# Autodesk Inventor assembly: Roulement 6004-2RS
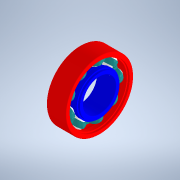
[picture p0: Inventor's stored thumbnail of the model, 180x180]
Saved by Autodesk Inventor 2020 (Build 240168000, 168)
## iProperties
Created: 2003-06
Part Number: Roulement 6004-2RS
Document SubType Name: Assembly
Designer: Bruno
Author: Bruno
Sending System: SolidWorks 2011
Last Author: Professeur
Last Saved: 2014-11-10
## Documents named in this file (5)
- D:\Téléchargements-2016-17\scoot_elec\pièces à assembler\ROULEMENT 6004-2RS\Roulement 6004-2RS.iam
- D:\Téléchargements-2016-17\scoot_elec\pièces à assembler\ROULEMENT 6004-2RS\Bague intérieure 6004-2RS.ipt
- D:\Téléchargements-2016-17\scoot_elec\pièces à assembler\ROULEMENT 6004-2RS\Cage 6004-2RS.ipt
- D:\Téléchargements-2016-17\scoot_elec\pièces à assembler\ROULEMENT 6004-2RS\Billes 6004-2RS.ipt
- D:\Téléchargements-2016-17\scoot_elec\pièces à assembler\ROULEMENT 6004-2RS\Bague extérieure 6004-2RS.iam
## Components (12 placed, 4 different names)
1. Bague intérieure 6004-2RS:1
2. Cage 6004-2RS:1
3. Billes 6004-2RS:1
4. Billes 6004-2RS:2
5. Billes 6004-2RS:3
6. Billes 6004-2RS:4
7. Billes 6004-2RS:5
8. Billes 6004-2RS:6
9. Billes 6004-2RS:7
10. Billes 6004-2RS:8
11. Billes 6004-2RS:9
12. Bague extérieure 6004-2RS:1 [sub-assembly]
